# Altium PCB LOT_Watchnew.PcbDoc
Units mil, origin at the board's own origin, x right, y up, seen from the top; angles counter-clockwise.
Board outline 1575 x 1355 mil, 2 copper layers (Top Layer, Bottom Layer); 31 components, 27 nets, 136 pads, 23 vias.
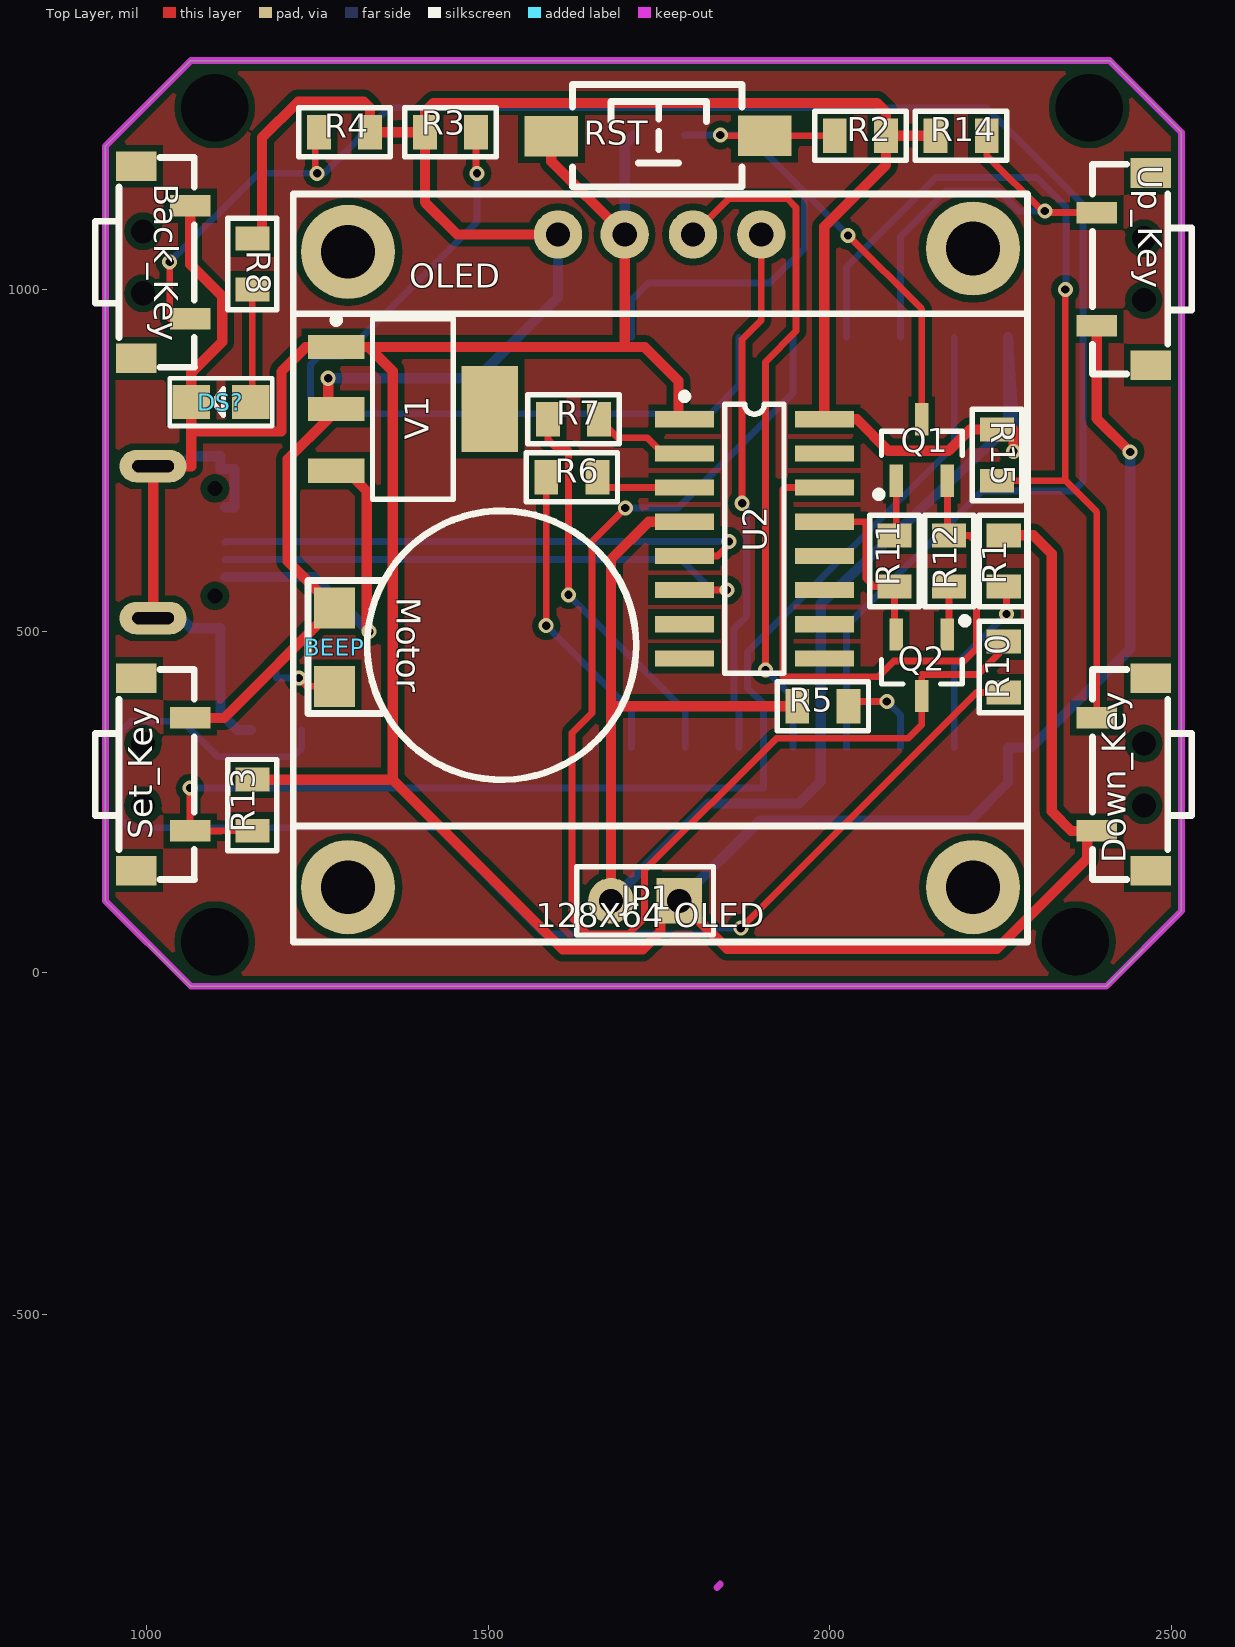
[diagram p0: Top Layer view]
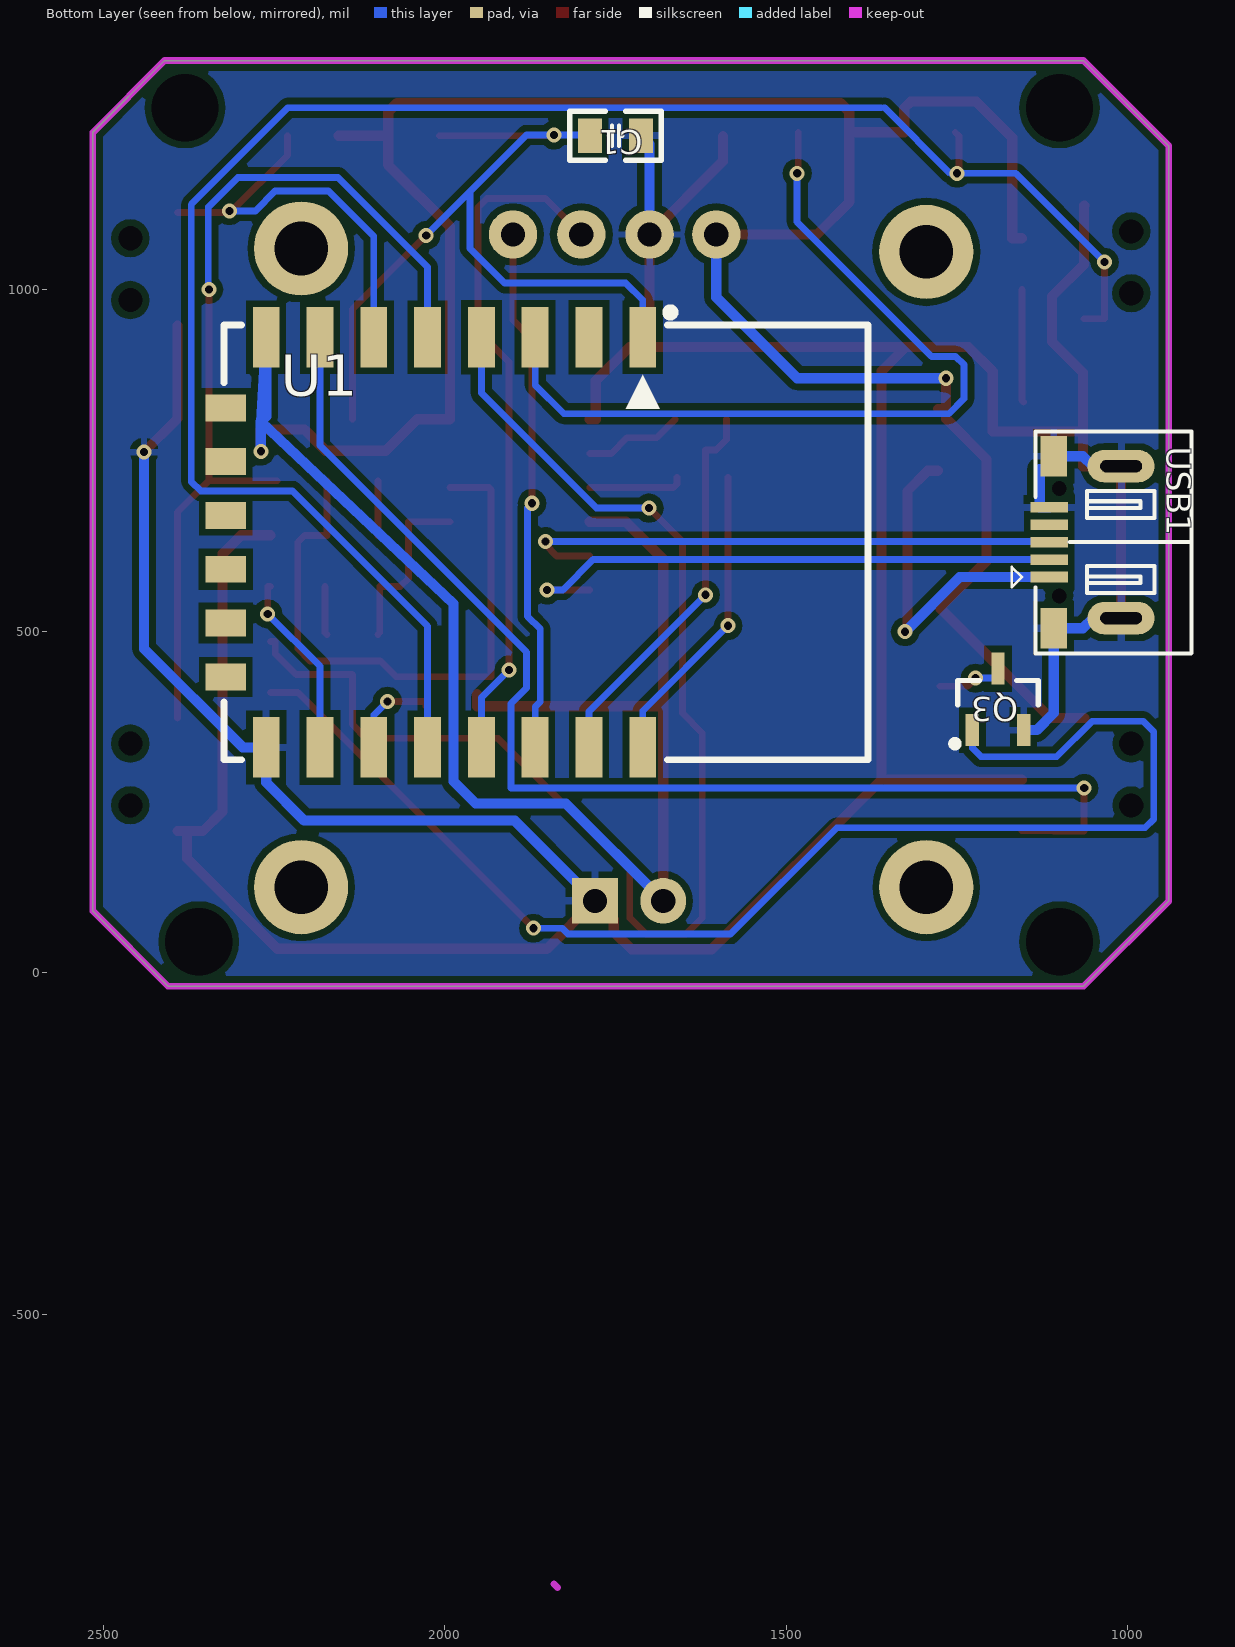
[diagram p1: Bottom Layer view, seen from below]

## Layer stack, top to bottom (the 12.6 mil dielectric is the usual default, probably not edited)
Top Solder: solder mask 0.4, Solder Resist, Dk 3.5
Top Layer: signal copper 1.4
Dielectric 1: dielectric 12.6, FR-4, Dk 4.8
Bottom Layer: signal copper 1.4
Bottom Solder: solder mask 0.4, Solder Resist, Dk 3.5

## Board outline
1065,-20 940,105 940,1210 1065,1335 2410,1335 2515,1230 2515,90 2405,-20

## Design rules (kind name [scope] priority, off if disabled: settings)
Clearance [All] p1: gap=10 ignorepadtopadclearanceinfootprint=FALSE except(0: Arc-Hole Track-Hole SMDPad-Hole THPad-Hole Via-Hole Fill-Hole Poly-Hole Region-Hole Text-Hole)
PolygonConnect [All] p1: connectstyle=Relief reliefconductorwidth=10 reliefentries=4 polygonreliefangle="90 Angle" airgapwidth=10
RoutingVias [All] p1: holewidth=12 width=22 viastyle="Through Hole" minholewidth=12 minwidth=22 maxholewidth=12 maxwidth=22
SilkToSilkClearance [All] p1: silktosilkclearance=2
SilkToSolderMaskClearance [IsPad] p1: minsilkscreentomaskgap=2 clearancetoexposedcopper=TRUE
SolderMaskExpansion [All] p1: expansion=4
Width Power [InNetClass('POWER')] p1: maxlimit=20 minlimit=15 preferedwidth=15 minimp=50.000000 maximp=50.000000 favimp=50.000000
Width [All] p2: maxlimit=10 minlimit=10 preferedwidth=10
28 further rules are at their usual default settings.

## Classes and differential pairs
net class Power: GND VCC3.3 VCC5

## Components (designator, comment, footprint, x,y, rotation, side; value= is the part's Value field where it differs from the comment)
Back_Key "3x6x5" "TSW 3*6*4.3-S-W" 995,1039.72 r270 top
BEEP "BEEP" 震动马达 1520,479.02 r270 top
C1 "100nF" "C 0805_L" 1750,1225 r0 bottom
Down_Key "3x6x5" "TSW 3*6*4.3-S-W" 2460,290 r90 top
DS? "LED1" SMDLED 1152.63,834.94 r180 top
JP1 "HDR-1X2" HDR2.54-M-LI-2P 1730,105 r180 top
OLED "JLX 0.96_128X64" 0.96_I2C_OLED 1217.5,1139.49 r0 top
Q1 "SS8050" SOT23-3N 2135,765 r0 top
Q2 "SS8050" SOT23-3N 2135,449.96 r180 top
Q3 "SS8050" SOT23-3N 1190,400 r180 bottom
R1 "10K" "R 0805_L" 2255,602.6 r90 top
R2 "10k" "R 0805_L" 2045,1225 r0 top
R3 "10K" "R 0805_L" 1445,1230 r180 top
R4 "10K" "R 0805_L" 1290,1230 r0 top
R5 "10K" "R 0805_L" 1990,389.96 r0 top
R6 "300" "R 0805_L" 1622.6,725 r180 top
R7 "300" "R 0805_L" 1625,810 r180 top
R8 "680" "R 0805_L" 1155,1037.4 r270 top
R10 "4.7K" "R 0805_L" 2255,447.4 r270 top
R11 "10k" "R 0805_L" 2095,602.6 r90 top
R12 "10k" "R 0805_L" 2175,602.6 r270 top
R13 "10k" "R 0805_L" 1155,245 r90 top
R14 "10k" "R 0805_L" 2192.6,1225 r180 top
R15 "10k" "R 0805_L" 2245,757.4 r90 top
RST "3x6x5" "TSW SMD-3*6*2.5" 1750,1225 r0 top
Set_Key "3x6x5" "TSW 3*6*4.3-S-W" 995,290 r270 top
U1 "ESP8266-12E" ESP_12E 1710,944.76 r270 bottom
U2 "CH340C" SOP16M 1890,634.96 r270 top
Up_Key "3x6x5" "TSW 3*6*4.3-S-W" 2460,1029.72 r90 top
USB1 "USB-5P" USB-MICRO_B 1010,630 r90 bottom
V1 "AMS1117-3V3" SOT223_L 1390,825 r0 top

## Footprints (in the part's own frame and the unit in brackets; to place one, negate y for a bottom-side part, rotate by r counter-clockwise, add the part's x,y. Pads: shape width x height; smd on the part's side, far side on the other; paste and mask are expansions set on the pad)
0.96_I2C_OLED [mm]
  round 3.5 hole 2: 0(1.968,-25.768) 0(1.968,-2.146) 0(25.209,-25.768) 0(25.209,-2.019)
  round 1.8 hole 0.9: 1(9.777,-1.5) 2(12.255,-1.5) 3(14.795,-1.5) 4(17.335,-1.5)
  silkscreen extent -0.06,-27.8 27.24,0, body extent -0.06,-27.8 27.24,0, height 2.7
"C 0805_L" [mil] "无极性贴片电容"
  rect 35x50 smd: 1(-37.4,0) 2(37.4,0)
  silkscreen extent -67,-36 67,36, body extent -39,-24 39,24, height 20
ESP_12E [mm] "ESP-12 Wi-Fi Module by AI-Thinker"
  rect 2.25x1 smd: 1(0.375,0) 2(0.375,-2) 3(0.375,-4) 4(0.375,-6) 5(0.375,-8) 6(0.375,-10) 7(0.375,-12) 8(0.375,-14) 15(15.625,-14) 16(15.625,-12) 17(15.625,-10) 18(15.625,-8) 19(15.625,-6) 20(15.625,-4) 21(15.625,-2) 22(15.625,0)
  rect 1x1.5 smd: 9(3,-15.5) 10(5,-15.5) 11(7,-15.5) 12(9,-15.5) 13(11,-15.5) 14(13,-15.5)
  silkscreen extent -0.7,-15.57 16.08,8.37, body extent 0,-15.49 16,8.51, height 2.75
HDR2.54-M-LI-2P [mm] "排母，2脚"
  rect 1.7x1.7 hole 0.9: 1(-1.27,0)
  round 1.7 hole 0.9: 2(1.27,0)
  silkscreen extent -2.54,-1.27 2.54,1.27, body extent -2.54,-1.27 2.54,1.27, height 8.5
"R 0805_L" [mil] "1/8W贴片电阻"
  rect 35x50 smd: 1(-37.4,0) 2(37.4,0)
  silkscreen extent -67,-36 67,36, body extent -39,-25 39,25, height 20
SMDLED [mm]
  rect 1.4x1.27 smd: 1(0.001,-0.002) 2(2.211,-0.002)
  silkscreen extent -0.8,-0.89 3.01,0.89
SOP16M [mm]
  rect 0.6x2.2 smd: 1(-4.445,-2.6) 2(-3.175,-2.6) 3(-1.905,-2.6) 4(-0.635,-2.6) 5(0.635,-2.6) 6(1.905,-2.6) 7(3.175,-2.6) 8(4.445,-2.6) 9(4.445,2.6) 10(3.175,2.6) 11(1.905,2.6) 12(0.635,2.6) 13(-0.635,2.6) 14(-1.905,2.6) 15(-3.175,2.6) 16(-4.445,2.6)
  silkscreen extent -5.42,-2.72 5,1.1
SOT23-3N [mm] "3x1.3x1mm(长宽高)"
  rect 0.5x1.2 smd: 1(-0.95,-1.143) 2(0.95,-1.143) 3(0,1.143)
  silkscreen extent -1.72,-1.78 1.5,0.7, body extent -1.5,-1.2 1.5,1.2, height 1.05
SOT223_L [mm] "SOT223, 4-Leads, Body 6.5x3.5mm, Pitch 2.3mm, Lead Span 7mm, IPC High Density"
  rect 2.1x0.9 smd: 1(-2.85,2.3) 2(-2.85,0) 3(-2.85,-2.3)
  rect 2.1x3.2 smd: 4(2.85,0)
  silkscreen extent -2.97,-3.35 1.5,3.42, body extent -1.85,-3.35 1.85,3.35, height 1.7
"TSW 3*6*4.3-S-W" [mm] "侧立贴片3*6*4.3"
  rect 1.1x1.5 smd: 0(-3.575,-0.25) 0(3.575,-0.25)
  round 0 hole 0.9: 0(-1.15,0) 0(1.15,0)
  rect 0.8x1.5 smd: 1(2.1,1.75) 2(-2.1,1.75)
  silkscreen extent -3.9,-1.78 3.9,1.91, body extent -3.9,-1.79 3.9,1.91, height 3.51
"TSW SMD-3*6*2.5" [mm] "3*6*2.5mm"
  rect 2x1.5 smd: 1(-3.996,-0.02) 2(3.937,0)
  silkscreen extent -3.21,-1.9 3.09,1.9, body extent -4,-1.88 4,1.62, height 2.59
USB-MICRO_B [mm] "micro型USB ，5.9*8.2*2.5mm"
  round 0 hole 0.55 unplated: 0(-2,2.294) 0(2,2.294)
  rect 0.394x1.4 smd: 1(-1.295,2.667) 2(-0.648,2.667) 3(0,2.667) 4(0.648,2.667) 5(1.295,2.667)
  rect 1.5x1 smd: 5(-3.2,2.5) 5(3.2,2.5)
  oval 1.2x2.5 hole 0.45 slot 1.55 at 90 deg: 5(-2.825,-0.006) 5(2.825,-0.006)
  silkscreen extent -4.14,-2.63 4.11,4.06, body extent -4,-2.72 4,2.88, height 2.8
震动马达 [mil]
  rect 60x60 smd: 1(-55,-245) 2(60,-245)
  silkscreen extent -197,-284 197,197

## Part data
Back_Key Down_Key RST Set_Key Up_Key: library part "TSW 3x6", "3x6轻触开关"
C1: library part C, "无极性贴片电容"
DS?: library part LED2, "Typical RED, GREEN, YELLOW, AMBER GaAs LED", PackageDocument=Feb-2002
JP1: library part "Header 2", "2P接插件"
OLED: "0.96寸OLED显示屏"
Q1 Q2 Q3: library part 8050-SMD, "高频放大-NPN型"
R1 R2 R3 R4 R5 R6 R7 R8 R10 R11 R12 R13 R14 R15: library part R, "贴片电阻"
U1: "串口 WIFI模块，ESP-12E"
U2: library part CH340G, "USB2UART"
USB1: "微型USB母座"
V1: library part AMS1117, "三端稳压芯片"

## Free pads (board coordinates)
  round 0 hole 98.43: 0(1100,45) 0(1100,1266) 0(2360,45) 0(2380,1266)

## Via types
v1: diameter 22, hole 12, Top Layer to Bottom Layer, 23 vias

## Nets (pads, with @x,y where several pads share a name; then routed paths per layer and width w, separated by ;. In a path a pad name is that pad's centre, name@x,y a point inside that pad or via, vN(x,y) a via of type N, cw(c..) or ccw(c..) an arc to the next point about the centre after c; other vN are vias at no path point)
Back_key: Back_Key.1 R4.1 U1.18 | length 2678.9
  Top Layer w10: v1(1034,1040) 1034,957.05 Back_Key.1 ; v1(1250,1170) 1247,1170 1247,1224.4 R4.1
  Bottom Layer w10: v1(1034,1040) 1164,1170 v1(1250,1170) 1260,1170 1356,1266 ; 1361,1266 2229.05,1266 2371,1124.05 2371,719 2356.95,704.95 2222.91,704.95 2024.96,507 U1.18
CH340RXD: R6.1 U2.3 | length 139.7
  Top Layer w10: R6.1 1660,715 1665.04,709.96 U2.3
CH340TXD: R7.1 U2.2 | length 146
  Top Layer w10: R7.1 1689.41,783 1732.96,783 1756,759.96 U2.2
D+: U2.5 USB1.3 | length 814.2
  Top Layer w10: U2.5 1835.96,609.96 1852.57,626.57 v1(1852.57,631)
  Bottom Layer w10: USB1.3 1116,631 v1(1852.57,631)
D-: U2.6 USB1.2 | length 815.8
  Top Layer w10: U2.6 v1(1850,559.96)
  Bottom Layer w10: USB1.2 1782.5,604.5 1827.04,559.96 v1(1850,559.96)
Down_key: Down_Key.1 R15.1 U1.5 | length 1363.8
  Top Layer w10: R15.1 2345,720 ; v1(2345,1000) 2345,720 ; Down_Key.1 2391.1,673.9 2345,720
  Bottom Layer w10: U1.5 2024.96,1033 2155.96,1164 2302.77,1164 2346,1120.77 2346,1001 v1(2345,1000)
DTR: Q2.2 R11.1 U2.13 | length 261.7
  Top Layer w10: U2.13 2053,659.96 2053,577.2 2065,565.2 R11.1 2095,497.56 Q2.2
GND: Back_Key.2 C1.1 Down_Key.2 DS?.2 JP1.1 OLED.2 Q3.2 R1.2 R13.2 RST.1 U1.15 U2.1 Up_Key.2 USB1.5 V1.1 | length 6602.6
  Top Layer w15: USB1.5@1009.78,518.78 1010,518.78 USB1.5@1010,741.22 ; USB1.5@1009.78,741.22 USB1.5@1010,741.22 ; Back_Key.2 1064,1122.4 1064,1037 1111,990 1111,923.41 1065.59,878 DS?.2 1065.59,792 ; R13.2 1354.5,282.4 ; RST.1 1592.69,1187.75 OLED.2 1700,915.55 ; U2.1 1778.64,809.96 1778.64,866.36 1729.45,915.55 1700,915.55 ; R1.2 2298,640 2325,613 2325,236 2353.68,207.32 Down_Key.2@2377,207.32 ; Down_Key.2 Down_Key.2@2377,207.32 ; Up_Key.2 2391.1,810.9 v1(2440,762) ; USB1.5@1010,741.22 1065.59,741.22 1065.59,792 ; 1065.59,792 1197.66,792 1197.66,880 1233.21,915.55 V1.1 1325.45,915.55 ; 1325.45,915.55 1360.6,880.4 1360.6,282.4 1608.97,34.03 1726.43,34.03 1752.4,60 1752.4,77.4 JP1.1 1850,35 2245,35 2377,167 Down_Key.2@2377,207.32 ; 1325.45,915.55 1700,915.55
  Bottom Layer w15: USB1.5@1009.78,518.78 1051,518.78 1065.76,504.02 1108.42,504.02 1108.42,380 1133.42,355 Q3.2 ; USB1.5@1009.78,741.22 1051,741.22 1065.76,755.98 1108.42,755.98 1108.42,737 1129,737 1129,681 USB1.5@1115,681 ; OLED.2 1700,1212.41 C1.1 ; JP1.1 1897.5,222.5 2205.5,222.5 2261.18,278.18 U1.15 2295.61,329.61 2440,474 v1(2440,762)
GPIO0: Q2.3 R10.1 U1.4 | length 1942.4
  Top Layer w10: v1(1701,680) 1652,631 1652,380 1623,351 1623,80 1646.47,56.53 1705.53,56.53 1729,80 1729,150 1922,343 2115,343 2135,363 Q2.3 2135,436.34 2217.25,436.34 2248,467.09 2248,484.8 R10.1
  Bottom Layer w10: v1(1701,680) 1778,680 1946.22,848.22 U1.4
NetBEEP_2: BEEP.2 Q3.3 | length 104
  Top Layer w10: v1(1222.98,431) 1234.97,419.02 BEEP.2
  Bottom Layer w10: Q3.3 1190,431 v1(1222.98,431)
NetDS?_1: DS?.1 R8.2 | length 166
  Top Layer w10: DS?.1 1155,837.4 R8.2
NetQ1_1: Q1.1 R11.2 | length 82.6
  Top Layer w10: R11.2 2097.6,640 Q1.1
NetQ2_1: Q2.1 R12.2 | length 71.3
  Top Layer w10: Q2.1 2175,497.56 R12.2
NetQ3_1: Q3.1 R10.2 | length 1961.5
  Top Layer w10: v1(1870,65) 2215,410 R10.2
  Bottom Layer w10: Q3.1 1227.4,328.4 1215,316 1104,316 1052.01,367.99 977.99,367.99 962,352 962,225 975,212 1426,212 1581.46,56.54 1819.68,56.54 1828.14,65 v1(1870,65)
NetR1_1: R1.1 U1.16 | length 271.3
  Top Layer w10: R1.1 2259,565.2 v1(2259,525)
  Bottom Layer w10: U1.16 2182.44,448.44 v1(2259,525)
NetR3_1: R3.1 U1.3 | length 1236.2
  Top Layer w10: R3.1 1482.4,1171.6 v1(1484,1170)
  Bottom Layer w10: v1(1484,1170) 1484,1099 1287,902 1252,902 1240,890 1240,840 1262,818 1825.48,818 1867.48,860 U1.3
NetR5_2: R5.2 U1.17 | length 139
  Top Layer w10: R5.2 2027.4,397 v1(2083.7,397)
  Bottom Layer w10: v1(2083.7,397) 2103.7,377 U1.17
NetR6_2: R6.2 U1.22 | length 447.1
  Top Layer w10: v1(1585.2,507.8) R6.2
  Bottom Layer w10: v1(1585.2,507.8) 1710,383 U1.22
NetR7_2: R7.2 U1.21 | length 572.7
  Top Layer w10: R7.2 1587.6,780 1602.6,765 1618,765 v1(1618,553)
  Bottom Layer w10: v1(1618,553) 1788.74,382.26 U1.21
nRST: C1.2 Q1.3 R2.1 RST.2 U1.1 | length 1204.3
  Top Layer w10: v1(1840,1226) 1841,1225 RST.2 1956,1225 R2.1 ; v1(2027,1079) 2135,971 Q1.3
  Bottom Layer w10: U1.1 1710,984.29 1735,1009.29 1912.29,1009.29 1963,1060 1963,1142 ; C1.2@1787.4,1226 C1.2 1788.39,1226 v1(1840,1226) 1880,1226 v1(2027,1079)
OLED_SCL: OLED.3 U1.19 | length 1003.9
  Top Layer w10: OLED.3 1852.57,1133 1938,1133 1951,1120 1951,939 1906,894 v1(1906,443)
  Bottom Layer w10: v1(1906,443) 1946.22,402.78 U1.19
OLED_SDA: OLED.4 U1.20 | length 775.9
  Top Layer w10: v1(1872,687) 1872,927 1900,955 OLED.4
  Bottom Layer w10: U1.20 1867.48,389.07 1860,396.55 1860,503 1878.57,521.57 1878.57,680.43 v1(1872,687)
RTS: Q1.2 R12.1 U2.14 | length 918.1
  Top Layer w10: U2.14 1934.96,709.96 1932,707 1932,433 2070.66,433 2094,456.34 2197,456.34 2215,474.34 2215,630 2205,640 R12.1 2172.4,640 Q1.2
Set_key: R13.1 Set_Key.1 U1.7 | length 1787.8
  Top Layer w10: v1(1063.9,270) Set_Key.1 1109,207.32 1109.27,207.6 R13.1
  Bottom Layer w10: v1(1063.9,270) 1903,270 1903,393.55 1880,416.55 1880,469 2182.44,771.44 U1.7
Up_key: R14.1 U1.6 Up_Key.1 | length 626.6
  Top Layer w10: R14.1 2230,1196.3 2313.9,1112.4 v1@2317.6,1112.4 ; v1(2315,1115) v1@2317.6,1112.4 ; Up_Key.1 2360.4,1112.4 v1@2317.6,1112.4
  Bottom Layer w10: U1.6 2103.7,1077.6 2170,1143.9 2248.1,1143.9 2277,1115 v1(2315,1115)
VCC3.3: BEEP.1 JP1.2 OLED.1 R2.2 R3.2 R4.2 R5.1 R8.1 R14.2 R15.2 Set_Key.2 U1.8 U2.4 U2.16 V1.2 | length 5792.2
  Top Layer w15: Set_Key.2 1113.66,372.68 BEEP.1 1207,602.02 1207,751.84 1266,810.84 V1.2@1266,825 ; R8.1 1169,1074.8 1169,1222 1222,1275 1318,1275 1327.4,1265.6 R4.2 1367,1230 R3.2 ; v1(1266,870) V1.2@1266,825 ; V1.2 V1.2@1266,825 ; OLED.1 1455,1080.43 1407.6,1127.83 R3.2 ; JP1.2 1680,389.96 R5.1 R5.1@1952.6,407.46 ; 1680,390 1680,604.96 1735,659.96 U2.4 ; R14.2 2118,1225 R2.2 ; v1(2269,763) 2269,794.8 R15.2 2205,794.8 2174.2,764 2086,764 2040.04,809.96 U2.16 1992,809.96 1992,1091.58 2082.4,1181.98 R2.2 ; R3.2 1407.6,1260 1420.6,1273 2069.4,1273 2082.4,1260 R2.2
  Bottom Layer w15: v1(1266,870) 1484,870 1602.4,988.4 OLED.1 ; JP1.2 1822.5,247.5 1954.69,247.5 1987,279.81 1987,540 2269,806.18 ; v1(2269,763) 2269,806.18 ; 2269,806.18 U1.8 2261.18,814 2269,806.18
VCC5: USB1.1 V1.3 | length 508.5
  Top Layer w15: V1.3 1293,734.45 1322.5,704.95 1322.5,502.5 v1(1326,499)
  Bottom Layer w15: USB1.1 1246,579 v1(1326,499)
pads on no net: Back_Key.0 Down_Key.0 OLED.0 Set_Key.0 U1.2 U1.9 U1.10 U1.11 U1.12 U1.13 U1.14 U2.7 U2.8 U2.9 U2.10 U2.11 U2.12 U2.15 Up_Key.0 USB1.0 USB1.4 V1.4

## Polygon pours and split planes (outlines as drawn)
no net on Top Layer "Top Layer-No Net" (solid, pour order 6): 1070,1335 2410,1335 2410,1330 2515,1225 2515,90 2405,-20 1065,-20 940,105 940,1210
no net on Top Layer "Top Layer-No Net 1" (solid, pour order 4): 1065,1335
GND on Bottom Layer "Bottom Layer-GND" (solid, pour order 8): 2407.5,1335 2512.5,1230 2515,1230 2515,90 2405,-20 1065,-20 940,105 940,1210 1065,1335

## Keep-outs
Keep-Out Layer:
  rectangle: 2730,-315 2735,-310
  lines w10: 1835,-900 1840,-895 ; 940,105 940,1210 ; 940,105 1065,-20 ; 940,105 940,1210 ; 940,105 1065,-20 ; 940,1210 1065,1335 ; 940,1210 1065,1335 ; 1065,-20 2405,-20 ; 1065,-20 1130,-20 2405,-20 ; 1065,1335 2410,1335 ; 1065,1335 2410,1335 ; 2405,-20 2515,90 ; 2405,-20 2515,90 ; 2410,1335 2515,1230 ; 2410,1335 2515,1230 ; 2515,90 2515,1230 ; 2515,90 2515,1230

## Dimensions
940,1210 to 2515,1230 on Top Overlay
1065,1335 to 1065,-20 on Top Overlay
